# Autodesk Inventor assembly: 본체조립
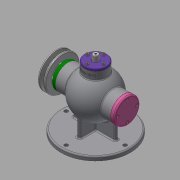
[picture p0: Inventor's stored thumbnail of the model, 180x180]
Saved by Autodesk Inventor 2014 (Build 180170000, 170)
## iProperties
Created: 2020-08
Part Number: 본체조립
Document SubType Name: Assembly
Designer: kh
Author: kh
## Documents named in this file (18)
- C:\Users\kh\Desktop\700806V1034\본체조립.iam
- C:\Users\kh\Desktop\700806V1034\본체.ipt
- C:\Users\kh\Desktop\700806V1034\V-벨트풀리.ipt
- C:\Users\kh\Desktop\700806V1034\너트 M8.ipt
- C:\Users\kh\Desktop\700806V1034\뒤커버.ipt
- C:\Users\kh\Desktop\700806V1034\멈춤링 15x1.ipt
- C:\Users\kh\Desktop\700806V1034\멈춤링 35x1.6.ipt
- 멈춤링 35x1.6.ipt
- C:\Users\kh\Desktop\700806V1034\베어링 6202.ipt
- 베어링 6202.ipt
- C:\Users\kh\Desktop\700806V1034\볼트 M4.ipt
- C:\Users\kh\Desktop\700806V1034\상부커버.ipt
- C:\Users\kh\Desktop\700806V1034\슬라이드.ipt
- C:\Users\kh\Desktop\700806V1034\앞커버.ipt
- C:\Users\kh\Desktop\700806V1034\오일 실 15 30 7.ipt
- C:\Users\kh\Desktop\700806V1034\칼라.ipt
- C:\Users\kh\Desktop\700806V1034\키 3x3x12.ipt
- C:\Users\kh\Desktop\700806V1034\편심축.ipt
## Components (1 placed, 1 different names)
1. V-벨트풀리:1 — Insert:11, Mate:8, Insert:15
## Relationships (3: Insert 2, Mate 1)
- Insert:11: V-벨트풀리:1
- Mate:8: V-벨트풀리:1
- Insert:15: V-벨트풀리:1
